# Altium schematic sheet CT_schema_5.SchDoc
size 430 x 429 mm
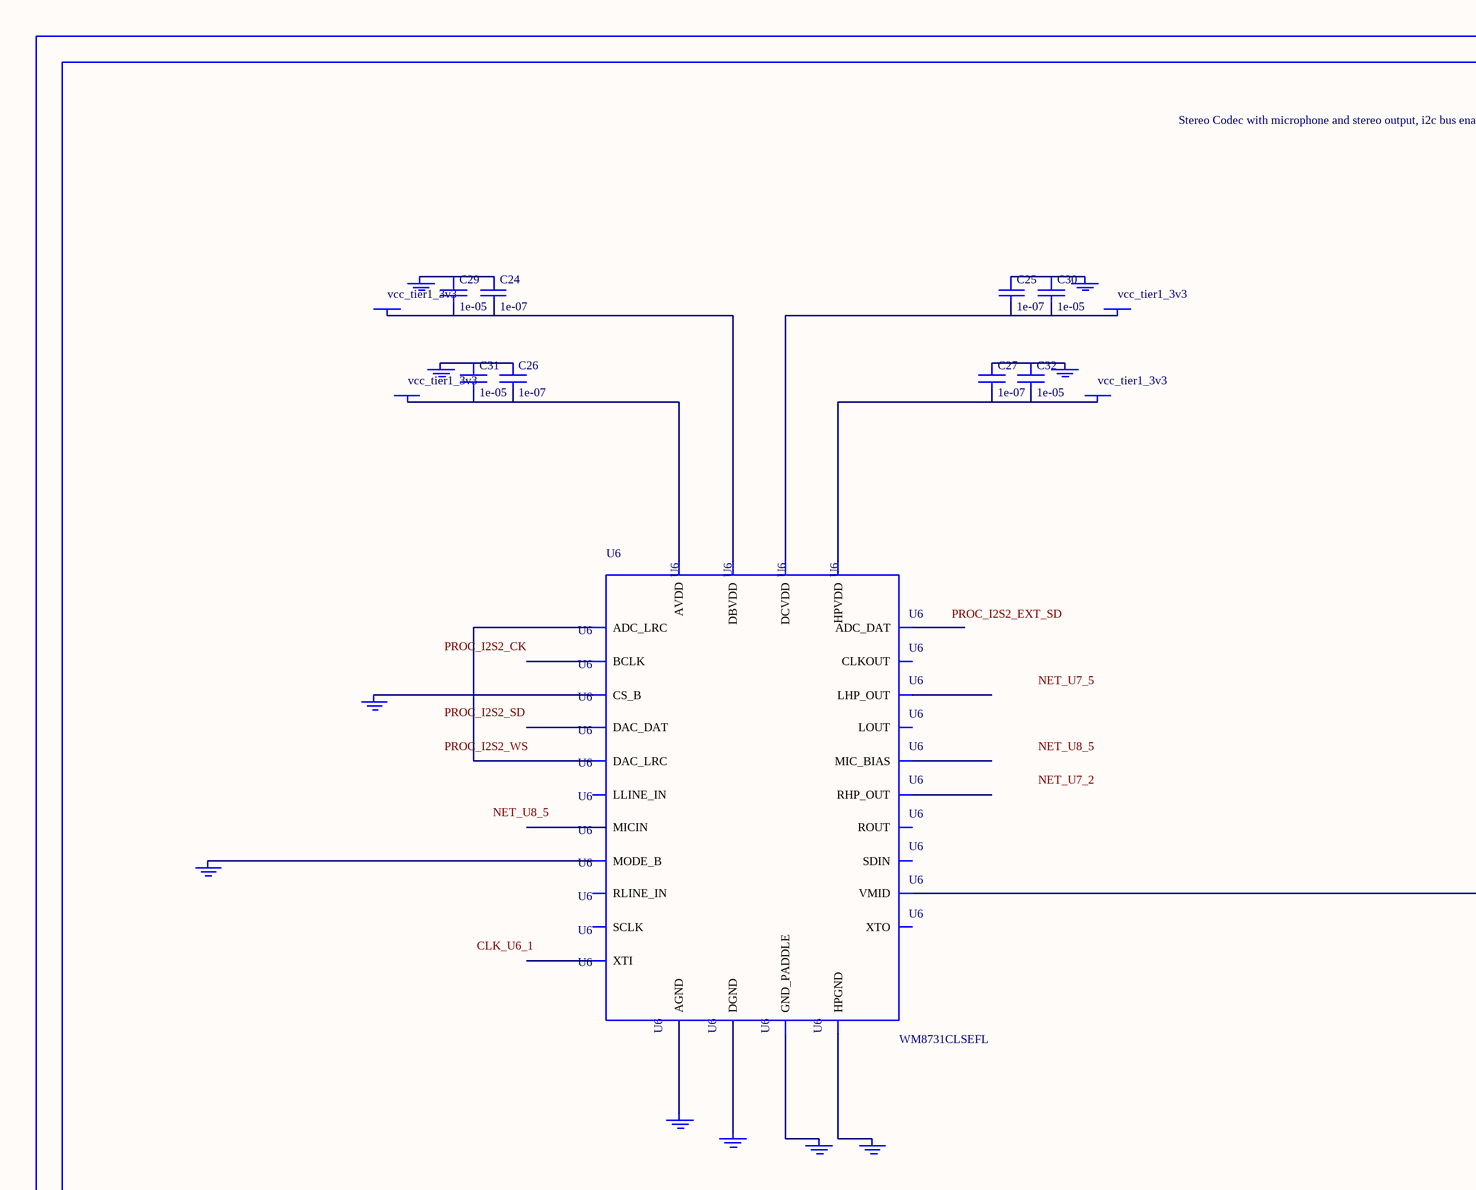
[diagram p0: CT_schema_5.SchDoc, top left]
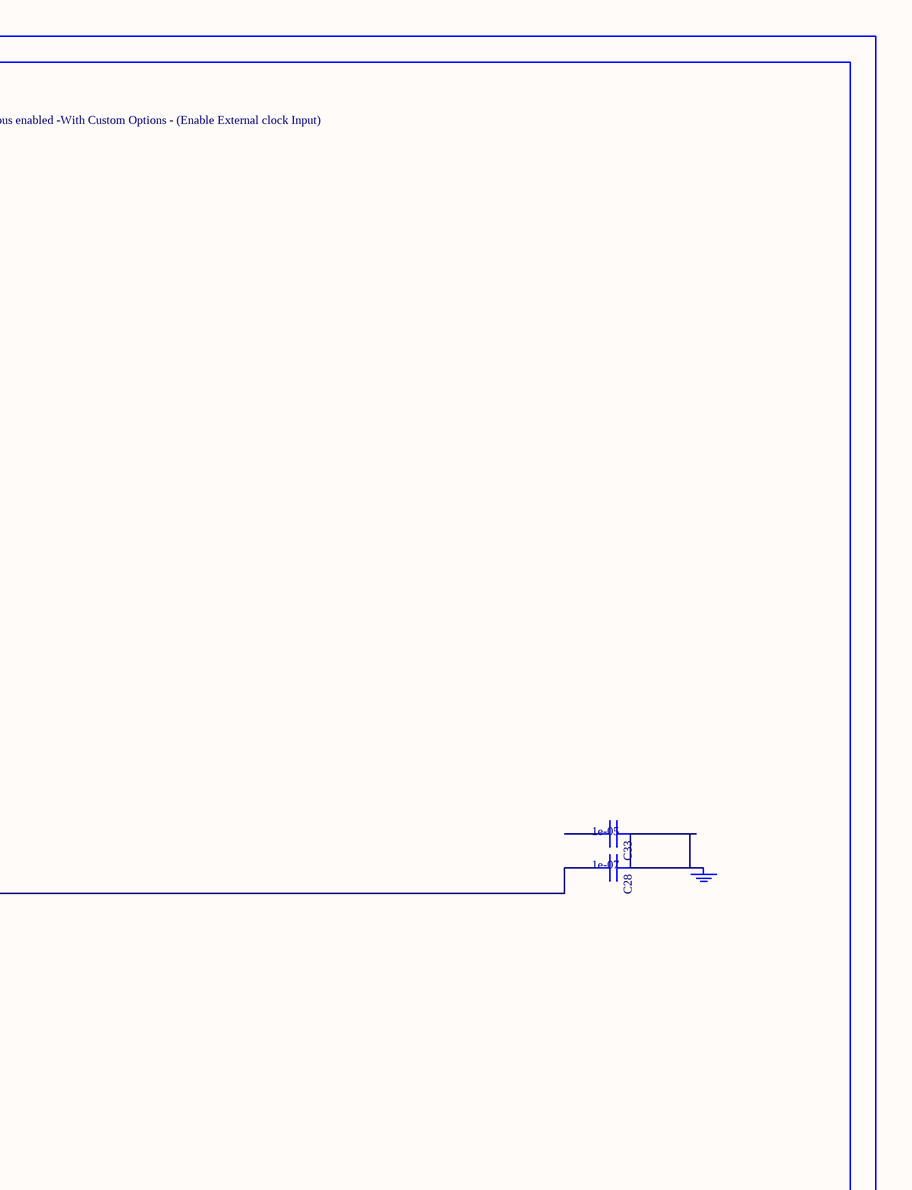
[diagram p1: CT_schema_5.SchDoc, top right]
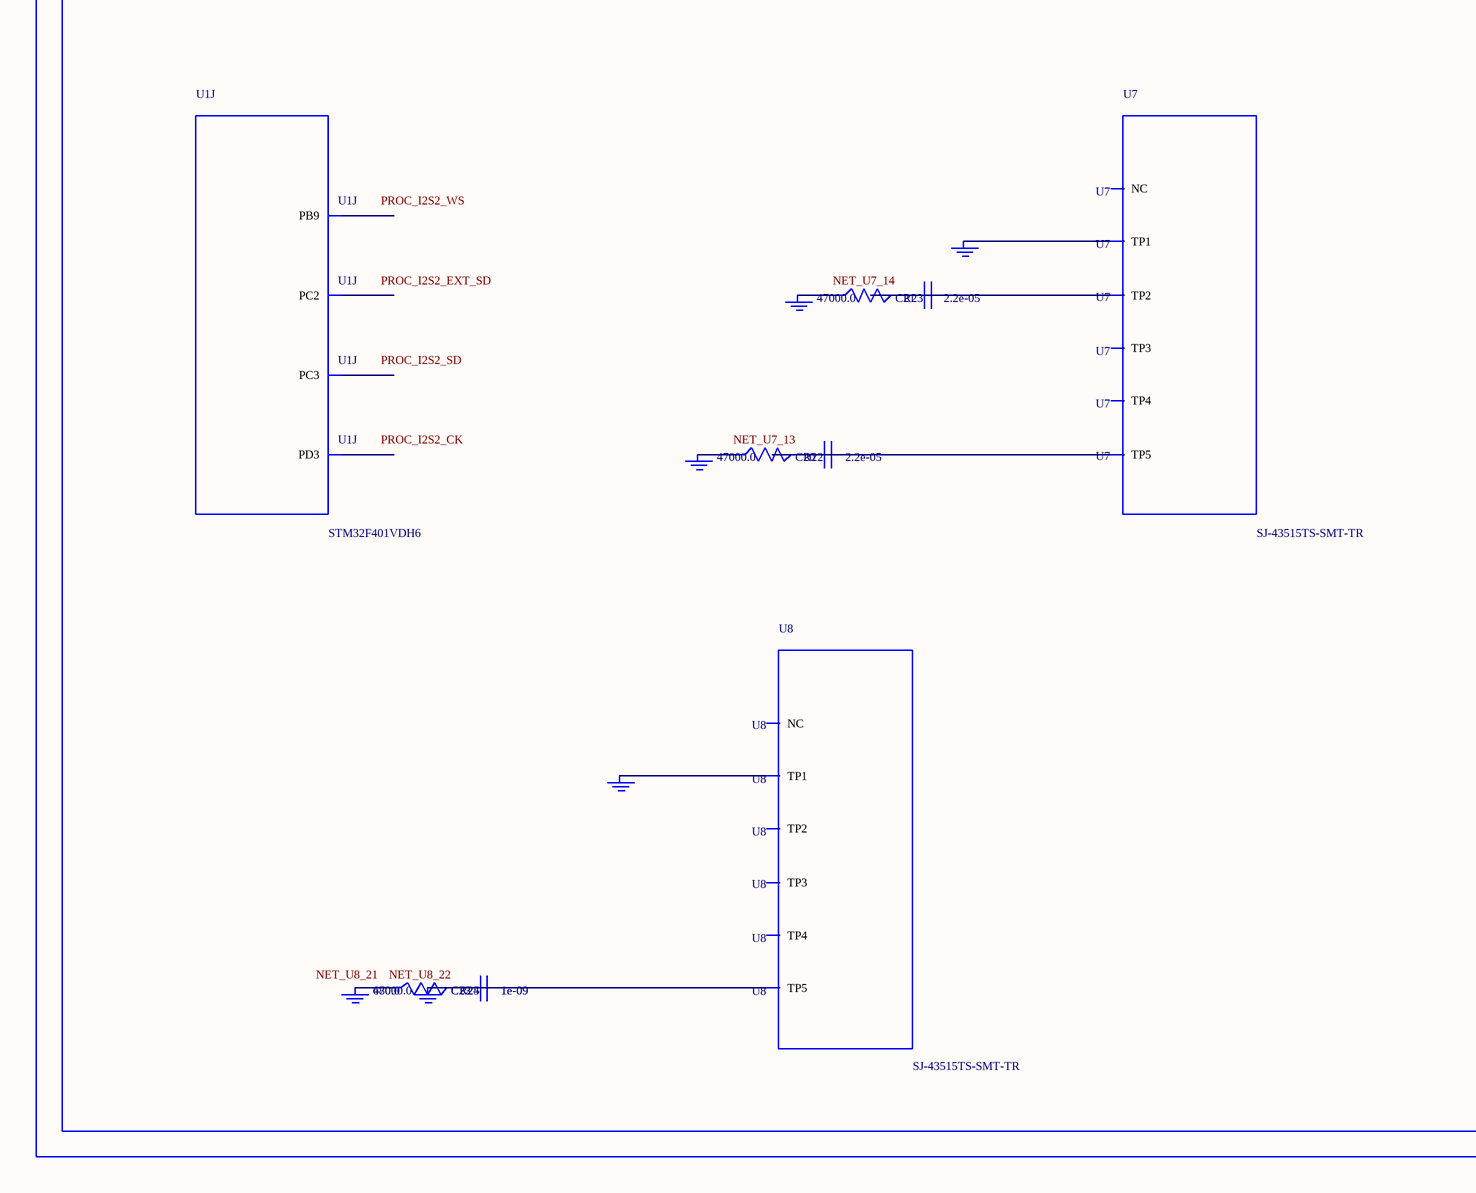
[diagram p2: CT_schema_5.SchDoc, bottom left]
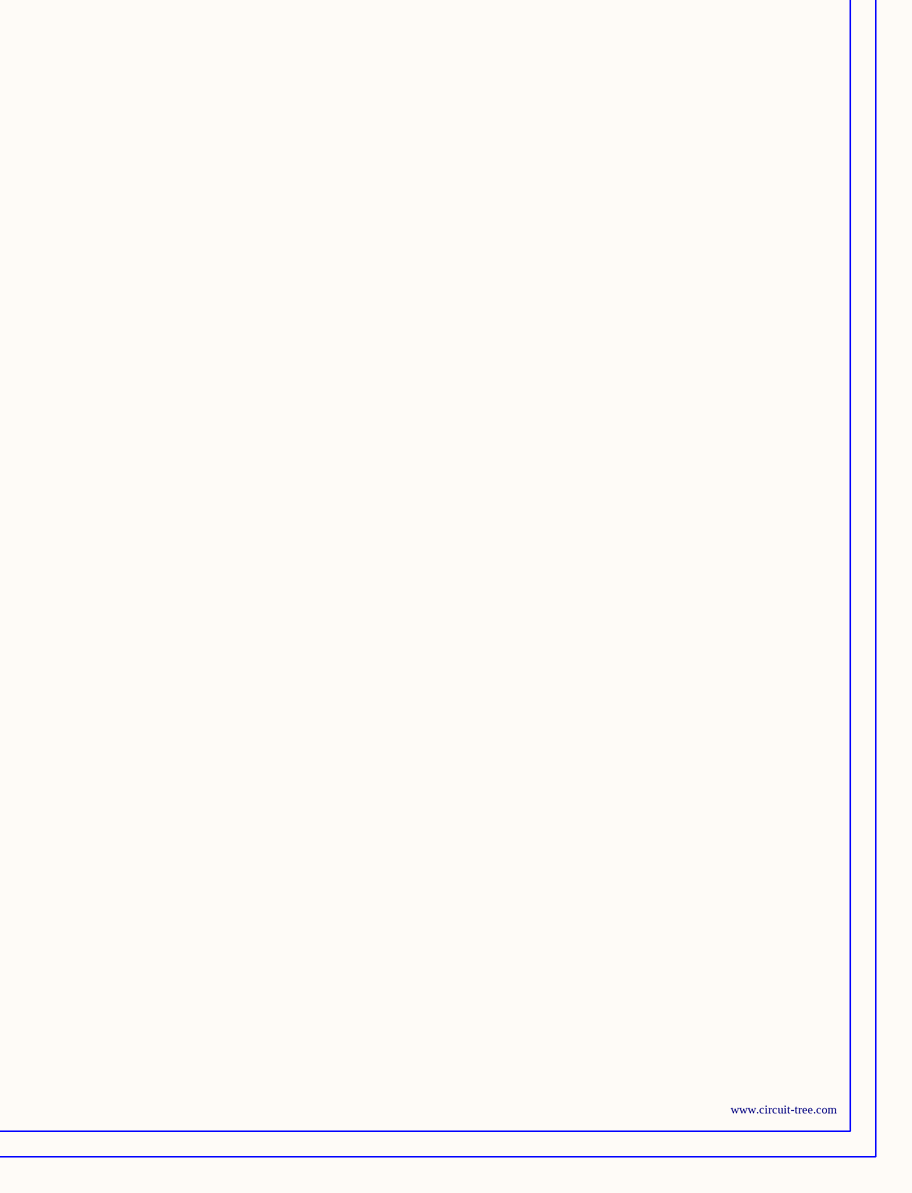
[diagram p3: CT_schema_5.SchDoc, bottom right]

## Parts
BORDER4  (no value)
C20  2.2e-05  [C1210]
C21  2.2e-05  [C1210]
C22  1e-09  [C0402]
C23  1e-09  [C0402]
C24  1e-07  [C0402]
C25  1e-07  [C0402]
C26  1e-07  [C0402]
C27  1e-07  [C0402]
C28  1e-07  [C0402]
C29  1e-05  [C0805]
C30  1e-05  [C0805]
C31  1e-05  [C0805]
C32  1e-05  [C0805]
C33  1e-05  [C0805]
GND_INSTANCE_4_0  (no value)
GND_INSTANCE_4_1  (no value)
GND_INSTANCE_4_2  (no value)
GND_INSTANCE_4_3  (no value)
GND_INSTANCE_4_4  (no value)
GND_INSTANCE_4_5  (no value)
GND_INSTANCE_4_6  (no value)
GND_INSTANCE_4_7  (no value)
GND_INSTANCE_4_8  (no value)
GND_INSTANCE_4_9  (no value)
GND_INSTANCE_4_10  (no value)
GND_INSTANCE_4_11  (no value)
GND_INSTANCE_4_12  (no value)
GND_INSTANCE_4_13  (no value)
GND_INSTANCE_4_14  (no value)
GND_INSTANCE_4_15  (no value)
GND_INSTANCE_4_16  (no value)
POWER_INSTANCE_4_0  vcc_tier1_3v3
POWER_INSTANCE_4_1  vcc_tier1_3v3
POWER_INSTANCE_4_2  vcc_tier1_3v3
POWER_INSTANCE_4_3  vcc_tier1_3v3
R22  47000.0  [R0603]
R23  47000.0  [R0603]
R24  47000.0  [R0603]
R25  680.0  [R0603]
U1  STM32F401VDH6  [UFBGA100]  (part J of 10)
U6  WM8731CLSEFL  [QFN-28]
U7  SJ-43515TS-SMT-TR  [SJ-43515TS-SMT-TR]
U8  SJ-43515TS-SMT-TR  [SJ-43515TS-SMT-TR]

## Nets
NetC20_1: C20.1 C20.2 R22.2 U7.5(TP5)
NetC21_1: C21.1 C21.2 R23.2 U7.2(TP2)
NetC22_1: C22.1 C22.2 C23.1 C23.2 GND_INSTANCE_4_16.0(GND) R24.2 R25.2 U8.5(TP5)
NetC24_1: C24.1 C29.1 GND_INSTANCE_4_1.0(GND)
NetC24_2: C24.2 C29.2 POWER_INSTANCE_4_1.0(PWR) U6.5(DBVDD)
NetC25_1: C25.1 C30.1 GND_INSTANCE_4_0.0(GND)
NetC25_2: C25.2 C30.2 POWER_INSTANCE_4_0.0(PWR) U6.3(DCVDD)
NetC26_1: C26.1 C31.1 GND_INSTANCE_4_4.0(GND)
NetC26_2: C26.2 C31.2 POWER_INSTANCE_4_3.0(PWR) U6.18(AVDD)
NetC27_1: C27.1 C32.1 GND_INSTANCE_4_2.0(GND)
NetC27_2: C27.2 C32.2 POWER_INSTANCE_4_2.0(PWR) U6.12(HPVDD)
NetC28_1: C28.1 C33.1 GND_INSTANCE_4_5.0(GND)
NetC28_2: C28.2 U6.20(VMID)
NetGND_INSTANCE_4_3_0: GND_INSTANCE_4_3.0(GND) U6.15(HPGND)
NetGND_INSTANCE_4_6_0: GND_INSTANCE_4_6.0(GND) U6.25(MODE_B)
NetGND_INSTANCE_4_7_0: GND_INSTANCE_4_7.0(GND) U6.26(CS_B)
NetGND_INSTANCE_4_8_0: GND_INSTANCE_4_8.0(GND) U6.29(GND_PADDLE)
NetGND_INSTANCE_4_9_0: GND_INSTANCE_4_9.0(GND) U6.4(DGND)
NetGND_INSTANCE_4_10_0: GND_INSTANCE_4_10.0(GND) U6.19(AGND)
NetGND_INSTANCE_4_11_0: GND_INSTANCE_4_11.0(GND) U7.1(TP1)
NetGND_INSTANCE_4_12_0: GND_INSTANCE_4_12.0(GND) R23.1
NetGND_INSTANCE_4_13_0: GND_INSTANCE_4_13.0(GND) R22.1
NetGND_INSTANCE_4_14_0: GND_INSTANCE_4_14.0(GND) U8.1(TP1)
NetGND_INSTANCE_4_15_0: GND_INSTANCE_4_15.0(GND) R24.1 R25.1
NetU6_9: U6.9(DAC_LRC) U6.11(ADC_LRC)

Not connected (* = marked no-connect by the designer): C33 2; U1 B3(PB9) B8(PD3) J3(PC2) K2(PC3); U6 1(XTI) 2(XTO) 6(CLKOUT) 7(BCLK) 8(DAC_DAT) 10(ADC_DAT) 13(LHP_OUT) 14(RHP_OUT) 16(LOUT) 17(ROUT) 21(MIC_BIAS) 22(MICIN) 23(RLINE_IN) 24(LLINE_IN) 27(SDIN) 28(SCLK); U7 3(TP3) 4(TP4) 6(NC); U8 2(TP2) 3(TP3) 4(TP4) 6(NC)

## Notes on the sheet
- Labels drawn without touching a wire or pin: CLK_U6_1, NET_U7_2, NET_U7_5, NET_U7_13, NET_U7_14, NET_U8_5, NET_U8_21, NET_U8_22, PROC_I2S2_CK, PROC_I2S2_EXT_SD, PROC_I2S2_SD, PROC_I2S2_WS

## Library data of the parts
BORDER4 = BORDER_PAGE4
C20 C21 = C1210C224K5RACTU
C22 C23 = C0402C102K3RAC
C24-C28 = C0402C104K3RACTU
C29-C33 = C0805C106K8RACTU
GND_INSTANCE_4_0-GND_INSTANCE_4_16 = GND
POWER_INSTANCE_4_0-POWER_INSTANCE_4_3 = PWR
R22-R24 = RC0603JR-0747KL
R25 = RC0603JR-07680RL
